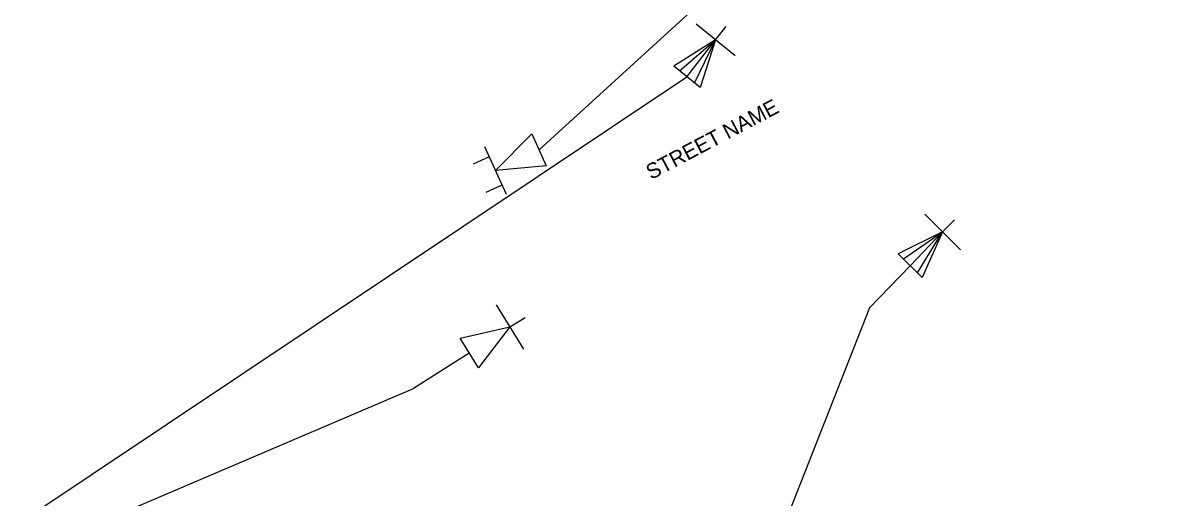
# Model space of a CAD drawing. Extents: x 1487362 to 2061618, y 497428 to 671257.
# Drawn here: x 1488473 to 1488623.4, y 499236.2 to 499298 of the extents above; entities that cross this region are included whole.
import ezdxf

# ---------------------------------------------------------------- set-up
doc = ezdxf.new("R2010")
doc.units = 0
for name, color, linetype in [('Exist Support 1', 7, 'Continuous'), ('Prop Support One', 7, 'Continuous'), ('Prop Support Two', 7, 'Continuous'), ('Scratch_Level_1', 7, 'Continuous')]:
    doc.layers.add(name, color=color, linetype=linetype)

msp = doc.modelspace()

# ---------------------------------------------------------------- linework, layer by layer
at = {"layer": 'Exist Support 1'}
for p, q in [((1488565.85, 499293.72), (1488560.73, 499297.85)), ((1488563.27, 499295.81), (1488564.67, 499297.55)), ((1488563.27, 499295.81), (1488557.82, 499292.38)), ((1488558.56, 499291.78), (1488563.27, 499295.81)), ((1488559.53, 499291), (1488563.27, 499295.81)), ((1488560.55, 499290.17), (1488563.27, 499295.81)), ((1488563.27, 499295.81), (1488561.26, 499289.6)), ((1488561.26, 499289.6), (1488557.82, 499292.38)), ((1488454.32, 499220.79), (1488559.53, 499291)), ((1488595.21, 499268.48), (1488590.53, 499273.11)), ((1488592.85, 499270.81), (1488594.43, 499272.4)), ((1488592.85, 499270.81), (1488587.08, 499267.96)), ((1488587.76, 499267.29), (1488592.85, 499270.81)), ((1488588.64, 499266.41), (1488592.85, 499270.81)), ((1488589.58, 499265.49), (1488592.85, 499270.81)), ((1488592.85, 499270.81), (1488590.22, 499264.85)), ((1488590.22, 499264.85), (1488587.08, 499267.96)), ((1488588.64, 499266.41), (1488583.33, 499260.94)), ((1488583.33, 499260.94), (1488557.34, 499194.94))]:
    msp.add_line(p, q, dxfattribs=at)
at = {"layer": 'Prop Support One'}
for p, q in [((1488540.27, 499281.48), (1488623.4, 499357.39)), ((1488538.28, 499255.52), (1488534.71, 499261.31)), ((1488536.48, 499258.44), (1488538.45, 499259.66)), ((1488529.99, 499256.98), (1488536.48, 499258.44)), ((1488536.48, 499258.44), (1488532.39, 499253.09)), ((1488532.39, 499253.09), (1488529.99, 499256.98)), ((1488531.19, 499255.03), (1488523.93, 499250.41)), ((1488454.32, 499220.79), (1488523.93, 499250.41))]:
    msp.add_line(p, q, dxfattribs=at)
at = {"layer": 'Prop Support Two'}
for p, q in [((1488534.58, 499278.78), (1488539.33, 499283.56)), ((1488539.33, 499283.56), (1488541.21, 499279.39)), ((1488533.17, 499281.91), (1488535.97, 499275.7)), ((1488533.78, 499280.57), (1488531.67, 499279.62)), ((1488541.21, 499279.39), (1488534.58, 499278.78)), ((1488535.43, 499276.9), (1488533.32, 499275.95))]:
    msp.add_line(p, q, dxfattribs=at)

# ---------------------------------------------------------------- texts
at = {"layer": 'Scratch_Level_1'}
msp.add_text('STREET NAME', height=2, rotation=27.8351, dxfattribs=at).set_placement((1488554.89, 499277.55))

doc.saveas('drawing.dxf')
